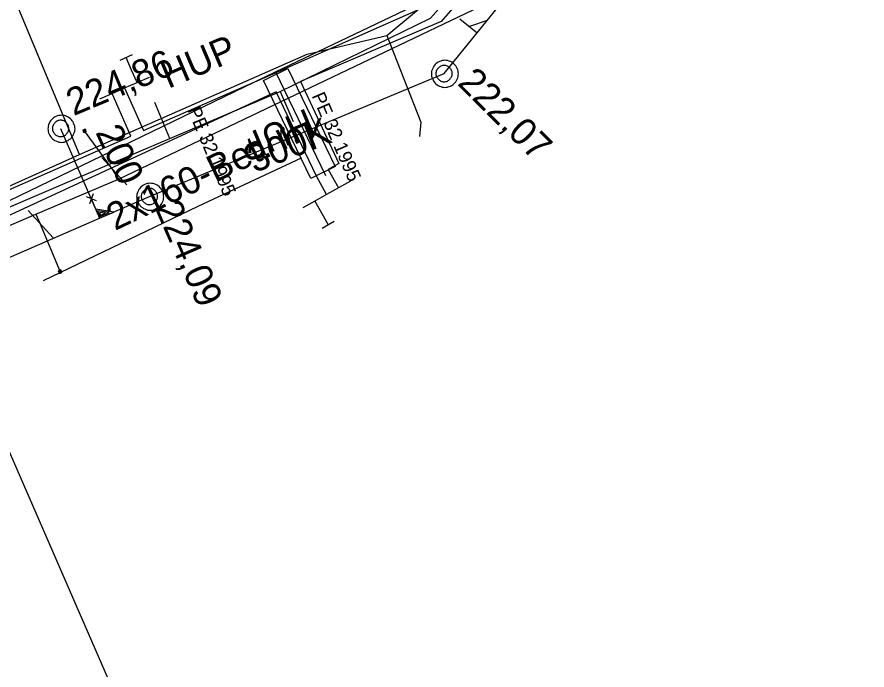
# Model space of a CAD drawing. Extents: x -746464 to -745690, y -1051581 to -1049993.
# Drawn here: x -746322.25 to -746290.95, y -1050869.96 to -1050845.94 of the extents above; entities that cross this region are included whole.
import ezdxf

# ---------------------------------------------------------------- set-up
doc = ezdxf.new("R2010")
doc.units = 0
for name, color, linetype in [('04_CETIN_sdelovaci_podzem', 7, 'Continuous'), ('48_Prazs_plynarenska_STL', 7, 'Continuous'), ('48_Prazs_plynarenska_STL_popisy', 7, 'Continuous'), ('51_PVaK_kanal_jednotna_neoverena poloha_pripojka', 7, 'Continuous'), ('51_PVaK_kanal_jednotna_overena poloha_rad', 7, 'Continuous'), ('51_PVaK_kanal_objekty', 7, 'Continuous'), ('51_PVaK_kanal_popisy', 7, 'Continuous'), ('51_PVaK_vodovod_chranicky_objekty', 7, 'Continuous'), ('51_PVaK_vodovod_overena poloha_pripojka', 7, 'Continuous'), ('51_PVaK_vodovod_overena poloha_rad', 7, 'Continuous'), ('55_PREdi_chranicky', 7, 'Continuous'), ('55_PREdi_NN', 7, 'Continuous'), ('55_PREdi_NN_pripojovaci_misto', 7, 'Continuous'), ('55_PREdi_stavby_popisy', 7, 'Continuous')]:
    doc.layers.add(name, color=color, linetype=linetype)

msp = doc.modelspace()

# ---------------------------------------------------------------- linework, layer by layer
at = {"layer": '04_CETIN_sdelovaci_podzem'}
for points in [[(-746308.63, -1050846.62), (-746304.41, -1050843.1), (-746300.25, -1050833.92)], [(-746319.94, -1050851), (-746322.71, -1050844.38), (-746323.87, -1050841.13), (-746318.41, -1050836.91), (-746319.27, -1050835.02)], [(-746319.94, -1050851), (-746311.56, -1050847.3), (-746308.63, -1050846.62)], [(-746308.63, -1050846.62), (-746307.38, -1050849.81)], [(-746308.63, -1050846.62), (-746307.38, -1050849.81), (-746307.43, -1050850.33)], [(-746331.37, -1050856.13), (-746319.94, -1050851)], [(-746339.9, -1050879.64), (-746338.45, -1050878.83), (-746318.88, -1050870.31), (-746322.85, -1050861.17)]]:
    msp.add_lwpolyline(points, dxfattribs=at)
at = {"layer": '48_Prazs_plynarenska_STL'}
for points in [[(-746346.15, -1050862.68), (-746338.94, -1050859.95), (-746330.71, -1050856.43), (-746318.76, -1050851.32), (-746316.62, -1050850.41), (-746312.56, -1050848.68), (-746307.02, -1050845.98), (-746303.88, -1050842.42), (-746301.4, -1050837.35), (-746294.27, -1050817.3), (-746287.43, -1050798.89), (-746287.287, -1050798.452)], [(-746312.56, -1050848.68), (-746312.083, -1050849.781)], [(-746316.62, -1050850.41), (-746317.177, -1050849.087)]]:
    msp.add_lwpolyline(points, dxfattribs=at)
at = {"layer": '51_PVaK_kanal_jednotna_neoverena poloha_pripojka'}
msp.add_line((-746320.64, -1050850.04), (-746319.204, -1050853.337), dxfattribs=at)
at = {"layer": '51_PVaK_kanal_jednotna_overena poloha_rad'}
for p, q in [((-746306.52, -1050848.02), (-746298.5, -1050838.14)), ((-746317.37, -1050852.54), (-746306.52, -1050848.02))]:
    msp.add_line(p, q, dxfattribs=at)
msp.add_lwpolyline([(-746344.54, -1050864.35), (-746339.747, -1050862.267), (-746323.698, -1050855.291), (-746319.204, -1050853.337), (-746317.37, -1050852.54)], dxfattribs=at)
at = {"layer": '51_PVaK_kanal_objekty'}
for p, q in [((-746319.314, -1050852.702), (-746319.686, -1050852.554)), ((-746319.439, -1050852.442), (-746319.579, -1050852.813))]:
    msp.add_line(p, q, dxfattribs=at)
for points in [[(-746305.938, -1050846.008), (-746305.304, -1050846.522), (-746304.938, -1050846.07), (-746305.59, -1050846.29)], [(-746305.99, -1050848.03), (-746306, -1050847.98), (-746306, -1050847.93), (-746306.02, -1050847.88), (-746306.04, -1050847.83), (-746306.06, -1050847.78), (-746306.09, -1050847.74), (-746306.12, -1050847.7), (-746306.16, -1050847.66), (-746306.2, -1050847.63), (-746306.24, -1050847.6), (-746306.29, -1050847.58), (-746306.34, -1050847.56), (-746306.39, -1050847.54), (-746306.44, -1050847.54), (-746306.49, -1050847.53), (-746306.54, -1050847.54), (-746306.59, -1050847.54), (-746306.64, -1050847.56), (-746306.69, -1050847.58), (-746306.74, -1050847.6), (-746306.78, -1050847.63), (-746306.82, -1050847.66), (-746306.86, -1050847.7), (-746306.89, -1050847.74), (-746306.92, -1050847.78), (-746306.94, -1050847.83), (-746306.96, -1050847.88), (-746306.98, -1050847.93), (-746306.98, -1050847.98), (-746306.99, -1050848.03), (-746306.98, -1050848.08), (-746306.98, -1050848.13), (-746306.96, -1050848.18), (-746306.94, -1050848.23), (-746306.92, -1050848.28), (-746306.89, -1050848.32), (-746306.86, -1050848.36), (-746306.82, -1050848.4), (-746306.78, -1050848.43), (-746306.74, -1050848.46), (-746306.69, -1050848.48), (-746306.64, -1050848.5), (-746306.59, -1050848.52), (-746306.54, -1050848.52), (-746306.49, -1050848.53), (-746306.44, -1050848.52), (-746306.39, -1050848.52), (-746306.34, -1050848.5), (-746306.29, -1050848.48), (-746306.24, -1050848.46), (-746306.2, -1050848.43), (-746306.16, -1050848.4), (-746306.12, -1050848.36), (-746306.09, -1050848.32), (-746306.06, -1050848.28), (-746306.04, -1050848.23), (-746306.02, -1050848.18), (-746306, -1050848.13), (-746306, -1050848.08), (-746305.99, -1050848.03)], [(-746306.22, -1050848.02), (-746306.22, -1050847.99), (-746306.226, -1050847.96), (-746306.232, -1050847.93), (-746306.244, -1050847.9), (-746306.262, -1050847.87), (-746306.28, -1050847.846), (-746306.298, -1050847.822), (-746306.322, -1050847.798), (-746306.346, -1050847.78), (-746306.37, -1050847.762), (-746306.4, -1050847.744), (-746306.43, -1050847.732), (-746306.46, -1050847.726), (-746306.49, -1050847.72), (-746306.52, -1050847.72), (-746306.55, -1050847.72), (-746306.58, -1050847.726), (-746306.61, -1050847.732), (-746306.64, -1050847.744), (-746306.67, -1050847.762), (-746306.694, -1050847.78), (-746306.718, -1050847.798), (-746306.742, -1050847.822), (-746306.76, -1050847.846), (-746306.778, -1050847.87), (-746306.796, -1050847.9), (-746306.808, -1050847.93), (-746306.814, -1050847.96), (-746306.82, -1050847.99), (-746306.82, -1050848.02), (-746306.82, -1050848.05), (-746306.814, -1050848.08), (-746306.808, -1050848.11), (-746306.796, -1050848.14), (-746306.778, -1050848.17), (-746306.76, -1050848.194), (-746306.742, -1050848.218), (-746306.718, -1050848.242), (-746306.694, -1050848.26), (-746306.67, -1050848.278), (-746306.64, -1050848.296), (-746306.61, -1050848.308), (-746306.58, -1050848.314), (-746306.55, -1050848.32), (-746306.52, -1050848.32), (-746306.49, -1050848.32), (-746306.46, -1050848.314), (-746306.43, -1050848.308), (-746306.4, -1050848.296), (-746306.37, -1050848.278), (-746306.346, -1050848.26), (-746306.322, -1050848.242), (-746306.298, -1050848.218), (-746306.28, -1050848.194), (-746306.262, -1050848.17), (-746306.244, -1050848.14), (-746306.232, -1050848.11), (-746306.226, -1050848.08), (-746306.22, -1050848.05), (-746306.22, -1050848.02)], [(-746320.11, -1050850.05), (-746320.12, -1050850), (-746320.12, -1050849.95), (-746320.14, -1050849.9), (-746320.16, -1050849.85), (-746320.18, -1050849.8), (-746320.21, -1050849.76), (-746320.24, -1050849.72), (-746320.28, -1050849.68), (-746320.32, -1050849.65), (-746320.36, -1050849.62), (-746320.41, -1050849.6), (-746320.46, -1050849.58), (-746320.51, -1050849.56), (-746320.56, -1050849.56), (-746320.61, -1050849.55), (-746320.66, -1050849.56), (-746320.71, -1050849.56), (-746320.76, -1050849.58), (-746320.81, -1050849.6), (-746320.86, -1050849.62), (-746320.9, -1050849.65), (-746320.94, -1050849.68), (-746320.98, -1050849.72), (-746321.01, -1050849.76), (-746321.04, -1050849.8), (-746321.06, -1050849.85), (-746321.08, -1050849.9), (-746321.1, -1050849.95), (-746321.1, -1050850), (-746321.11, -1050850.05), (-746321.1, -1050850.1), (-746321.1, -1050850.15), (-746321.08, -1050850.2), (-746321.06, -1050850.25), (-746321.04, -1050850.3), (-746321.01, -1050850.34), (-746320.98, -1050850.38), (-746320.94, -1050850.42), (-746320.9, -1050850.45), (-746320.86, -1050850.48), (-746320.81, -1050850.5), (-746320.76, -1050850.52), (-746320.71, -1050850.54), (-746320.66, -1050850.54), (-746320.61, -1050850.55), (-746320.56, -1050850.54), (-746320.51, -1050850.54), (-746320.46, -1050850.52), (-746320.41, -1050850.5), (-746320.36, -1050850.48), (-746320.32, -1050850.45), (-746320.28, -1050850.42), (-746320.24, -1050850.38), (-746320.21, -1050850.34), (-746320.18, -1050850.3), (-746320.16, -1050850.25), (-746320.14, -1050850.2), (-746320.12, -1050850.15), (-746320.12, -1050850.1), (-746320.11, -1050850.05)], [(-746320.34, -1050850.04), (-746320.34, -1050850.01), (-746320.346, -1050849.98), (-746320.352, -1050849.95), (-746320.364, -1050849.92), (-746320.382, -1050849.89), (-746320.4, -1050849.866), (-746320.418, -1050849.842), (-746320.442, -1050849.818), (-746320.466, -1050849.8), (-746320.49, -1050849.782), (-746320.52, -1050849.764), (-746320.55, -1050849.752), (-746320.58, -1050849.746), (-746320.61, -1050849.74), (-746320.64, -1050849.74), (-746320.67, -1050849.74), (-746320.7, -1050849.746), (-746320.73, -1050849.752), (-746320.76, -1050849.764), (-746320.79, -1050849.782), (-746320.814, -1050849.8), (-746320.838, -1050849.818), (-746320.862, -1050849.842), (-746320.88, -1050849.866), (-746320.898, -1050849.89), (-746320.916, -1050849.92), (-746320.928, -1050849.95), (-746320.934, -1050849.98), (-746320.94, -1050850.01), (-746320.94, -1050850.04), (-746320.94, -1050850.07), (-746320.934, -1050850.1), (-746320.928, -1050850.13), (-746320.916, -1050850.16), (-746320.898, -1050850.19), (-746320.88, -1050850.214), (-746320.862, -1050850.238), (-746320.838, -1050850.262), (-746320.814, -1050850.28), (-746320.79, -1050850.298), (-746320.76, -1050850.316), (-746320.73, -1050850.328), (-746320.7, -1050850.334), (-746320.67, -1050850.34), (-746320.64, -1050850.34), (-746320.61, -1050850.34), (-746320.58, -1050850.334), (-746320.55, -1050850.328), (-746320.52, -1050850.316), (-746320.49, -1050850.298), (-746320.466, -1050850.28), (-746320.442, -1050850.262), (-746320.418, -1050850.238), (-746320.4, -1050850.214), (-746320.382, -1050850.19), (-746320.364, -1050850.16), (-746320.352, -1050850.13), (-746320.346, -1050850.1), (-746320.34, -1050850.07), (-746320.34, -1050850.04)], [(-746316.84, -1050852.55), (-746316.85, -1050852.5), (-746316.85, -1050852.45), (-746316.87, -1050852.4), (-746316.89, -1050852.35), (-746316.91, -1050852.3), (-746316.94, -1050852.26), (-746316.97, -1050852.22), (-746317.01, -1050852.18), (-746317.05, -1050852.15), (-746317.09, -1050852.12), (-746317.14, -1050852.1), (-746317.19, -1050852.08), (-746317.24, -1050852.06), (-746317.29, -1050852.06), (-746317.34, -1050852.05), (-746317.39, -1050852.06), (-746317.44, -1050852.06), (-746317.49, -1050852.08), (-746317.54, -1050852.1), (-746317.59, -1050852.12), (-746317.63, -1050852.15), (-746317.67, -1050852.18), (-746317.71, -1050852.22), (-746317.74, -1050852.26), (-746317.77, -1050852.3), (-746317.79, -1050852.35), (-746317.81, -1050852.4), (-746317.83, -1050852.45), (-746317.83, -1050852.5), (-746317.84, -1050852.55), (-746317.83, -1050852.6), (-746317.83, -1050852.65), (-746317.81, -1050852.7), (-746317.79, -1050852.75), (-746317.77, -1050852.8), (-746317.74, -1050852.84), (-746317.71, -1050852.88), (-746317.67, -1050852.92), (-746317.63, -1050852.95), (-746317.59, -1050852.98), (-746317.54, -1050853), (-746317.49, -1050853.02), (-746317.44, -1050853.04), (-746317.39, -1050853.04), (-746317.34, -1050853.05), (-746317.29, -1050853.04), (-746317.24, -1050853.04), (-746317.19, -1050853.02), (-746317.14, -1050853), (-746317.09, -1050852.98), (-746317.05, -1050852.95), (-746317.01, -1050852.92), (-746316.97, -1050852.88), (-746316.94, -1050852.84), (-746316.91, -1050852.8), (-746316.89, -1050852.75), (-746316.87, -1050852.7), (-746316.85, -1050852.65), (-746316.85, -1050852.6), (-746316.84, -1050852.55)], [(-746317.07, -1050852.54), (-746317.07, -1050852.51), (-746317.076, -1050852.48), (-746317.082, -1050852.45), (-746317.094, -1050852.42), (-746317.112, -1050852.39), (-746317.13, -1050852.366), (-746317.148, -1050852.342), (-746317.172, -1050852.318), (-746317.196, -1050852.3), (-746317.22, -1050852.282), (-746317.25, -1050852.264), (-746317.28, -1050852.252), (-746317.31, -1050852.246), (-746317.34, -1050852.24), (-746317.37, -1050852.24), (-746317.4, -1050852.24), (-746317.43, -1050852.246), (-746317.46, -1050852.252), (-746317.49, -1050852.264), (-746317.52, -1050852.282), (-746317.544, -1050852.3), (-746317.568, -1050852.318), (-746317.592, -1050852.342), (-746317.61, -1050852.366), (-746317.628, -1050852.39), (-746317.646, -1050852.42), (-746317.658, -1050852.45), (-746317.664, -1050852.48), (-746317.67, -1050852.51), (-746317.67, -1050852.54), (-746317.67, -1050852.57), (-746317.664, -1050852.6), (-746317.658, -1050852.63), (-746317.646, -1050852.66), (-746317.628, -1050852.69), (-746317.61, -1050852.714), (-746317.592, -1050852.738), (-746317.568, -1050852.762), (-746317.544, -1050852.78), (-746317.52, -1050852.798), (-746317.49, -1050852.816), (-746317.46, -1050852.828), (-746317.43, -1050852.834), (-746317.4, -1050852.84), (-746317.37, -1050852.84), (-746317.34, -1050852.84), (-746317.31, -1050852.834), (-746317.28, -1050852.828), (-746317.25, -1050852.816), (-746317.22, -1050852.798), (-746317.196, -1050852.78), (-746317.172, -1050852.762), (-746317.148, -1050852.738), (-746317.13, -1050852.714), (-746317.112, -1050852.69), (-746317.094, -1050852.66), (-746317.082, -1050852.63), (-746317.076, -1050852.6), (-746317.07, -1050852.57), (-746317.07, -1050852.54)], [(-746319.521, -1050852.61), (-746319.205, -1050853.337), (-746318.686, -1050853.112), (-746319.347, -1050853.009)], [(-746319.277, -1050853.066), (-746319.185, -1050853.277), (-746318.854, -1050853.133), (-746319.281, -1050853.067)], [(-746319.206, -1050853.125), (-746319.16, -1050853.231), (-746318.99, -1050853.157), (-746319.21, -1050853.127)]]:
    msp.add_lwpolyline(points, dxfattribs=at)
at = {"layer": '51_PVaK_vodovod_chranicky_objekty'}
for p, q in [((-746319.822, -1050850.099), (-746319.803, -1050850.093)), ((-746319.822, -1050850.099), (-746319.695, -1050850.161)), ((-746319.822, -1050850.099), (-746319.815, -1050850.118)), ((-746319.789, -1050850.194), (-746319.796, -1050850.175)), ((-746319.728, -1050850.066), (-746319.789, -1050850.194)), ((-746319.789, -1050850.194), (-746319.77, -1050850.187)), ((-746319.728, -1050850.066), (-746319.746, -1050850.073)), ((-746319.728, -1050850.066), (-746319.721, -1050850.085)), ((-746319.695, -1050850.161), (-746319.714, -1050850.167)), ((-746319.695, -1050850.161), (-746319.701, -1050850.142)), ((-746318.204, -1050852.11), (-746319.122, -1050851.11)), ((-746320.914, -1050854.06), (-746321.832, -1050853.06)), ((-746320.725, -1050855.284), (-746320.706, -1050855.276)), ((-746320.725, -1050855.284), (-746320.594, -1050855.337)), ((-746320.725, -1050855.284), (-746320.717, -1050855.302)), ((-746320.686, -1050855.376), (-746320.694, -1050855.357)), ((-746320.632, -1050855.245), (-746320.686, -1050855.376)), ((-746320.686, -1050855.376), (-746320.668, -1050855.368)), ((-746320.632, -1050855.245), (-746320.651, -1050855.253)), ((-746320.632, -1050855.245), (-746320.625, -1050855.263)), ((-746320.594, -1050855.337), (-746320.612, -1050855.345)), ((-746320.594, -1050855.337), (-746320.602, -1050855.319))]:
    msp.add_line(p, q, dxfattribs=at)
for points in [[(-746319.742, -1050850.177), (-746319.737, -1050850.176), (-746319.733, -1050850.173), (-746319.729, -1050850.17), (-746319.724, -1050850.167), (-746319.721, -1050850.162), (-746319.718, -1050850.158), (-746319.715, -1050850.154), (-746319.713, -1050850.149), (-746319.711, -1050850.144), (-746319.71, -1050850.14), (-746319.708, -1050850.134), (-746319.708, -1050850.128), (-746319.709, -1050850.123), (-746319.71, -1050850.118), (-746319.711, -1050850.114), (-746319.713, -1050850.109), (-746319.715, -1050850.105), (-746319.718, -1050850.1), (-746319.722, -1050850.096), (-746319.726, -1050850.092), (-746319.73, -1050850.09), (-746319.734, -1050850.087), (-746319.739, -1050850.084), (-746319.744, -1050850.083), (-746319.749, -1050850.081), (-746319.755, -1050850.08), (-746319.76, -1050850.08), (-746319.765, -1050850.08), (-746319.77, -1050850.081), (-746319.775, -1050850.083), (-746319.78, -1050850.084), (-746319.784, -1050850.087), (-746319.788, -1050850.09), (-746319.792, -1050850.093), (-746319.796, -1050850.098), (-746319.799, -1050850.102), (-746319.802, -1050850.106), (-746319.804, -1050850.111), (-746319.806, -1050850.116), (-746319.807, -1050850.12), (-746319.808, -1050850.126), (-746319.809, -1050850.132), (-746319.808, -1050850.137), (-746319.807, -1050850.142), (-746319.806, -1050850.146), (-746319.804, -1050850.151), (-746319.801, -1050850.156), (-746319.799, -1050850.16), (-746319.795, -1050850.164), (-746319.791, -1050850.168), (-746319.787, -1050850.171), (-746319.783, -1050850.173), (-746319.777, -1050850.176), (-746319.773, -1050850.177), (-746319.768, -1050850.179), (-746319.762, -1050850.18), (-746319.757, -1050850.18), (-746319.752, -1050850.18), (-746319.747, -1050850.179), (-746319.742, -1050850.177)], [(-746320.64, -1050855.357), (-746320.635, -1050855.355), (-746320.631, -1050855.352), (-746320.627, -1050855.349), (-746320.623, -1050855.345), (-746320.62, -1050855.34), (-746320.617, -1050855.336), (-746320.615, -1050855.332), (-746320.612, -1050855.327), (-746320.611, -1050855.322), (-746320.61, -1050855.317), (-746320.609, -1050855.311), (-746320.609, -1050855.306), (-746320.61, -1050855.301), (-746320.611, -1050855.296), (-746320.613, -1050855.291), (-746320.615, -1050855.287), (-746320.618, -1050855.282), (-746320.621, -1050855.278), (-746320.625, -1050855.274), (-746320.629, -1050855.271), (-746320.634, -1050855.268), (-746320.638, -1050855.266), (-746320.643, -1050855.264), (-746320.648, -1050855.262), (-746320.653, -1050855.261), (-746320.659, -1050855.26), (-746320.664, -1050855.26), (-746320.669, -1050855.261), (-746320.674, -1050855.262), (-746320.679, -1050855.264), (-746320.683, -1050855.266), (-746320.687, -1050855.269), (-746320.692, -1050855.272), (-746320.696, -1050855.276), (-746320.699, -1050855.28), (-746320.701, -1050855.285), (-746320.704, -1050855.289), (-746320.706, -1050855.294), (-746320.707, -1050855.299), (-746320.709, -1050855.304), (-746320.709, -1050855.31), (-746320.709, -1050855.315), (-746320.708, -1050855.32), (-746320.707, -1050855.325), (-746320.705, -1050855.33), (-746320.703, -1050855.334), (-746320.701, -1050855.339), (-746320.698, -1050855.343), (-746320.694, -1050855.347), (-746320.689, -1050855.35), (-746320.685, -1050855.353), (-746320.681, -1050855.355), (-746320.675, -1050855.357), (-746320.671, -1050855.359), (-746320.666, -1050855.36), (-746320.66, -1050855.361), (-746320.655, -1050855.361), (-746320.65, -1050855.359), (-746320.645, -1050855.358), (-746320.64, -1050855.357)]]:
    msp.add_lwpolyline(points, dxfattribs=at)
at = {"layer": '51_PVaK_vodovod_overena poloha_pripojka'}
for p, q in [((-746318.7, -1050851.57), (-746319.76, -1050850.13)), ((-746318.51, -1050851.9), (-746318.7, -1050851.57)), ((-746321.55, -1050853.19), (-746321.41, -1050853.52)), ((-746321.41, -1050853.52), (-746320.66, -1050855.31))]:
    msp.add_line(p, q, dxfattribs=at)
at = {"layer": '51_PVaK_vodovod_overena poloha_rad'}
msp.add_lwpolyline([(-746346.29, -1050863.323), (-746337.33, -1050859.96), (-746324.926, -1050854.638), (-746321.55, -1050853.19), (-746318.51, -1050851.9), (-746304.63, -1050845.27), (-746302.59, -1050841.01), (-746298.68, -1050831.22), (-746293.24, -1050817.78), (-746288.11, -1050801.72), (-746287.5, -1050801.16)], dxfattribs=at)
at = {"layer": '55_PREdi_chranicky'}
msp.add_lwpolyline([(-746313.169, -1050848.273), (-746312.269, -1050847.838), (-746310.529, -1050851.439), (-746311.429, -1050851.874), (-746313.169, -1050848.273)], close=True, dxfattribs=at)
at = {"layer": '55_PREdi_NN'}
for points in [[(-746312.727, -1050847.959), (-746307.425, -1050845.426), (-746305.288, -1050843.133), (-746304.098, -1050841.922), (-746300.594, -1050833.849), (-746296.983, -1050823.675), (-746293.494, -1050813.845), (-746293.337, -1050813.403), (-746291.683, -1050809.616)], [(-746291.173, -1050810.118), (-746300.417, -1050835.746), (-746303.43, -1050842.43), (-746306.632, -1050846.103), (-746311.812, -1050848.316), (-746310.399, -1050851.329), (-746310.788, -1050851.544), (-746310.41, -1050852.223)], [(-746318.283, -1050848.549), (-746317.593, -1050850.12), (-746312.612, -1050847.939), (-746307.291, -1050845.586), (-746304.76, -1050842.681), (-746305.915, -1050841.676)], [(-746348.502, -1050862.556), (-746337.009, -1050858.225), (-746330.819, -1050855.691), (-746329.455, -1050855.56), (-746324.367, -1050853.543), (-746322.916, -1050852.879), (-746312.727, -1050847.959)], [(-746317.825, -1050848.348), (-746318.026, -1050847.89)], [(-746312.727, -1050847.959), (-746310.89, -1050851.764)], [(-746319.199, -1050848.95), (-746318.741, -1050848.749), (-746318.283, -1050848.549), (-746317.825, -1050848.348), (-746317.367, -1050848.147)], [(-746310.846, -1050852.467), (-746311.224, -1050851.788), (-746312.707, -1050848.693), (-746325.656, -1050854.671), (-746330.317, -1050856.486), (-746347.645, -1050863.054), (-746344.019, -1050872.234), (-746341.477, -1050871.245), (-746341.345, -1050871.603), (-746340.787, -1050871.396)], [(-746331.238, -1050854.464), (-746330.773, -1050855.673), (-746325.938, -1050853.777), (-746318.051, -1050850.321), (-746318.741, -1050848.749)], [(-746309.973, -1050851.98), (-746310.41, -1050852.223), (-746310.846, -1050852.467), (-746311.283, -1050852.71), (-746311.72, -1050852.953)], [(-746311.283, -1050852.71), (-746311.04, -1050853.147)]]:
    msp.add_lwpolyline(points, dxfattribs=at)
at = {"layer": '55_PREdi_NN_pripojovaci_misto'}
for p, q in [((-746318.001, -1050847.332), (-746318.458, -1050847.535)), ((-746318.026, -1050847.89), (-746318.229, -1050847.433)), ((-746311.04, -1050853.147), (-746310.79, -1050853.58)), ((-746311.007, -1050853.705), (-746310.573, -1050853.455))]:
    msp.add_line(p, q, dxfattribs=at)
at = {"layer": '55_PREdi_stavby_popisy'}
msp.add_lwpolyline([(-746321.271, -1050855.627), (-746315.576, -1050852.899), (-746311.771, -1050851.115)], dxfattribs=at)

# ---------------------------------------------------------------- texts
at = {"layer": '48_Prazs_plynarenska_STL_popisy'}
for s, height, rotation, p in [('HUP', 1, 23, (-746316.677, -1050848.587)), ('PE 32 1995', 0.5, 293.4243, (-746311.403, -1050848.836)), ('PE 32 1995', 0.5, 292.8317, (-746315.978, -1050849.357)), ('HUP', 1, 203, (-746311.583, -1050849.281))]:
    msp.add_text(s, height=height, rotation=rotation, dxfattribs=at).set_placement(p)
at = {"layer": '51_PVaK_kanal_popisy'}
for s, rotation, p in [('224,86', 22.6491, (-746320.165, -1050849.588)), ('222,07', 315.1109, (-746306.063, -1050848.407)), ('200', 294.5345, (-746319.37, -1050850.175)), ('300K', 21.6166, (-746313.503, -1050851.687)), ('224,09', 293.5861, (-746317.186, -1050852.945))]:
    msp.add_text(s, height=1, rotation=rotation, dxfattribs=at).set_placement(p)
at = {"layer": '55_PREdi_stavby_popisy'}
msp.add_text('2x160-Bet. r.', height=1, rotation=25.5928, dxfattribs=at).set_placement((-746318.64, -1050853.812))

doc.saveas('drawing.dxf')
